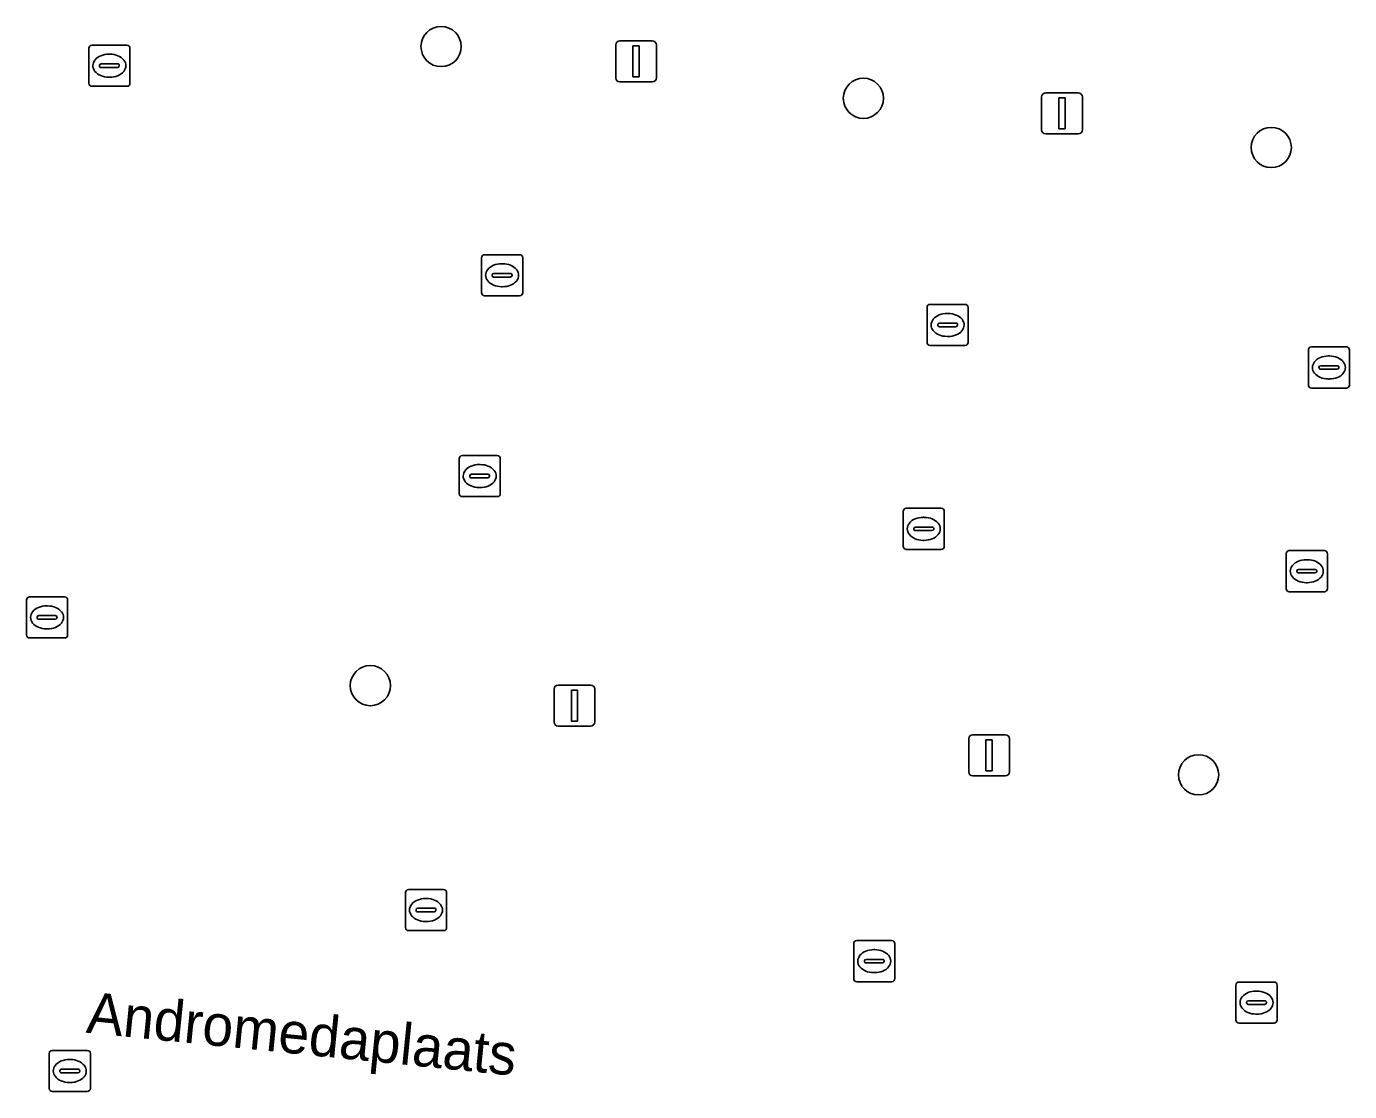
# Model space of a CAD drawing. Extents: x 161928 to 163071, y 386474 to 387428.
# Drawn here: x 162325.39 to 162357.55, y 386781.8 to 386807.71 of the extents above; entities that cross this region are included whole.
import ezdxf

# ---------------------------------------------------------------- set-up
doc = ezdxf.new("R2010")
doc.units = 0
for name, color, linetype in [('IMGEO_Boom', 7, 'Continuous'), ('IMGEO_Kolk', 7, 'Continuous'), ('IMGEO_Lichtmast', 7, 'Continuous'), ('IMGEO_Openbare_ruimte_label', 7, 'Continuous')]:
    doc.layers.add(name, color=color, linetype=linetype)

msp = doc.modelspace()

# ---------------------------------------------------------------- linework, layer by layer
at = {"layer": 'IMGEO_Boom'}
for centre in [(162335.468, 386807.22), (162345.734, 386805.961), (162355.649, 386804.765), (162333.748, 386791.675), (162353.882, 386789.504)]:
    msp.add_circle(centre, 0.489, dxfattribs=at)
at = {"layer": 'IMGEO_Kolk'}
for p, q in [((162326.902, 386806.328), (162326.902, 386807.18)), ((162326.977, 386807.254), (162327.829, 386807.254)), ((162327.39, 386807.034), (162327.415, 386807.034)), ((162327.903, 386807.18), (162327.903, 386806.328)), ((162327.161, 386806.748), (162327.161, 386806.76)), ((162327.599, 386806.711), (162327.201, 386806.711)), ((162327.204, 386806.797), (162327.602, 386806.797)), ((162327.645, 386806.76), (162327.645, 386806.748)), ((162327.413, 386806.474), (162327.388, 386806.474)), ((162327.829, 386806.254), (162326.977, 386806.254)), ((162336.45, 386801.231), (162336.45, 386802.083)), ((162336.525, 386802.157), (162337.377, 386802.157)), ((162336.938, 386801.937), (162336.963, 386801.937)), ((162337.451, 386802.083), (162337.451, 386801.231)), ((162336.709, 386801.651), (162336.709, 386801.663)), ((162337.147, 386801.614), (162336.749, 386801.614)), ((162336.752, 386801.7), (162337.15, 386801.7)), ((162337.193, 386801.663), (162337.193, 386801.651)), ((162336.961, 386801.377), (162336.936, 386801.377)), ((162337.377, 386801.157), (162336.525, 386801.157)), ((162347.356, 386800.948), (162348.208, 386800.948)), ((162347.281, 386800.022), (162347.281, 386800.874)), ((162347.769, 386800.728), (162347.794, 386800.728)), ((162348.282, 386800.874), (162348.282, 386800.022)), ((162347.54, 386800.442), (162347.54, 386800.454)), ((162347.978, 386800.405), (162347.58, 386800.405)), ((162347.583, 386800.491), (162347.981, 386800.491)), ((162348.024, 386800.454), (162348.024, 386800.442)), ((162348.208, 386799.948), (162347.356, 386799.948)), ((162347.792, 386800.168), (162347.767, 386800.168)), ((162356.551, 386798.987), (162356.551, 386799.839)), ((162356.626, 386799.913), (162357.478, 386799.913)), ((162357.039, 386799.693), (162357.064, 386799.693)), ((162357.552, 386799.839), (162357.552, 386798.987)), ((162356.81, 386799.407), (162356.81, 386799.419)), ((162357.248, 386799.37), (162356.85, 386799.37)), ((162356.853, 386799.456), (162357.251, 386799.456)), ((162357.294, 386799.419), (162357.294, 386799.407)), ((162357.062, 386799.133), (162357.037, 386799.133)), ((162357.478, 386798.913), (162356.626, 386798.913)), ((162335.905, 386796.346), (162335.905, 386797.198)), ((162335.98, 386797.272), (162336.832, 386797.272)), ((162336.393, 386797.052), (162336.418, 386797.052)), ((162336.906, 386797.198), (162336.906, 386796.346)), ((162336.164, 386796.766), (162336.164, 386796.778)), ((162336.602, 386796.729), (162336.204, 386796.729)), ((162336.207, 386796.815), (162336.605, 386796.815)), ((162336.648, 386796.778), (162336.648, 386796.766)), ((162336.416, 386796.492), (162336.391, 386796.492)), ((162336.832, 386796.272), (162335.98, 386796.272)), ((162346.7, 386795.062), (162346.7, 386795.914)), ((162346.775, 386795.988), (162347.627, 386795.988)), ((162347.188, 386795.768), (162347.213, 386795.768)), ((162347.701, 386795.914), (162347.701, 386795.062)), ((162346.959, 386795.482), (162346.959, 386795.494)), ((162347.397, 386795.445), (162346.999, 386795.445)), ((162347.002, 386795.531), (162347.4, 386795.531)), ((162347.443, 386795.494), (162347.443, 386795.482)), ((162347.211, 386795.208), (162347.186, 386795.208)), ((162347.627, 386794.988), (162346.775, 386794.988)), ((162356.013, 386794.032), (162356.013, 386794.884)), ((162356.088, 386794.958), (162356.94, 386794.958)), ((162357.014, 386794.884), (162357.014, 386794.032)), ((162356.272, 386794.452), (162356.272, 386794.464)), ((162356.315, 386794.501), (162356.713, 386794.501)), ((162356.501, 386794.738), (162356.526, 386794.738)), ((162356.756, 386794.464), (162356.756, 386794.452)), ((162356.71, 386794.415), (162356.312, 386794.415)), ((162356.524, 386794.178), (162356.499, 386794.178)), ((162325.462, 386793.834), (162326.314, 386793.834)), ((162356.94, 386793.958), (162356.088, 386793.958)), ((162325.387, 386792.908), (162325.387, 386793.76)), ((162325.875, 386793.614), (162325.9, 386793.614)), ((162326.388, 386793.76), (162326.388, 386792.908)), ((162325.646, 386793.328), (162325.646, 386793.34)), ((162326.084, 386793.291), (162325.686, 386793.291)), ((162325.689, 386793.377), (162326.087, 386793.377)), ((162326.13, 386793.34), (162326.13, 386793.328)), ((162325.898, 386793.054), (162325.873, 386793.054)), ((162326.314, 386792.834), (162325.462, 386792.834)), ((162334.6, 386785.789), (162334.6, 386786.641)), ((162334.675, 386786.715), (162335.527, 386786.715)), ((162335.088, 386786.495), (162335.113, 386786.495)), ((162335.601, 386786.641), (162335.601, 386785.789)), ((162334.859, 386786.209), (162334.859, 386786.221)), ((162335.297, 386786.172), (162334.899, 386786.172)), ((162334.902, 386786.258), (162335.3, 386786.258)), ((162335.343, 386786.221), (162335.343, 386786.209)), ((162335.111, 386785.935), (162335.086, 386785.935)), ((162335.527, 386785.715), (162334.675, 386785.715)), ((162345.573, 386785.472), (162346.425, 386785.472)), ((162345.498, 386784.546), (162345.498, 386785.398)), ((162345.986, 386785.252), (162346.011, 386785.252)), ((162346.499, 386785.398), (162346.499, 386784.546)), ((162345.757, 386784.966), (162345.757, 386784.978)), ((162346.195, 386784.929), (162345.797, 386784.929)), ((162345.8, 386785.015), (162346.198, 386785.015)), ((162346.241, 386784.978), (162346.241, 386784.966)), ((162346.009, 386784.692), (162345.984, 386784.692)), ((162346.425, 386784.472), (162345.573, 386784.472)), ((162354.791, 386783.537), (162354.791, 386784.389)), ((162354.866, 386784.463), (162355.718, 386784.463)), ((162355.279, 386784.243), (162355.304, 386784.243)), ((162355.792, 386784.389), (162355.792, 386783.537)), ((162355.05, 386783.957), (162355.05, 386783.969)), ((162355.488, 386783.92), (162355.09, 386783.92)), ((162355.093, 386784.006), (162355.491, 386784.006)), ((162355.534, 386783.969), (162355.534, 386783.957)), ((162355.302, 386783.683), (162355.277, 386783.683)), ((162355.718, 386783.463), (162354.866, 386783.463)), ((162325.94, 386781.874), (162325.94, 386782.726)), ((162326.015, 386782.8), (162326.867, 386782.8)), ((162326.428, 386782.58), (162326.453, 386782.58)), ((162326.941, 386782.726), (162326.941, 386781.874)), ((162326.199, 386782.294), (162326.199, 386782.306)), ((162326.637, 386782.257), (162326.239, 386782.257)), ((162326.242, 386782.343), (162326.64, 386782.343)), ((162326.683, 386782.306), (162326.683, 386782.294)), ((162326.451, 386782.02), (162326.426, 386782.02)), ((162326.867, 386781.8), (162326.015, 386781.8))]:
    msp.add_line(p, q, dxfattribs=at)
for points in [[(162326.902, 386806.328), (162326.902, 386807.18)], [(162326.977, 386807.254), (162327.829, 386807.254)], [(162327.903, 386807.18), (162327.903, 386806.328)], [(162327.829, 386806.254), (162326.977, 386806.254)], [(162336.45, 386801.231), (162336.45, 386802.083)], [(162336.525, 386802.157), (162337.377, 386802.157)], [(162337.451, 386802.083), (162337.451, 386801.231)], [(162337.377, 386801.157), (162336.525, 386801.157)], [(162347.356, 386800.948), (162348.208, 386800.948)], [(162347.281, 386800.022), (162347.281, 386800.874)], [(162348.282, 386800.874), (162348.282, 386800.022)], [(162348.208, 386799.948), (162347.356, 386799.948)], [(162356.551, 386798.987), (162356.551, 386799.839)], [(162356.626, 386799.913), (162357.478, 386799.913)], [(162357.552, 386799.839), (162357.552, 386798.987)], [(162357.478, 386798.913), (162356.626, 386798.913)], [(162335.905, 386796.346), (162335.905, 386797.198)], [(162335.98, 386797.272), (162336.832, 386797.272)], [(162336.906, 386797.198), (162336.906, 386796.346)], [(162336.832, 386796.272), (162335.98, 386796.272)], [(162346.7, 386795.062), (162346.7, 386795.914)], [(162346.775, 386795.988), (162347.627, 386795.988)], [(162347.701, 386795.914), (162347.701, 386795.062)], [(162347.627, 386794.988), (162346.775, 386794.988)], [(162356.013, 386794.032), (162356.013, 386794.884)], [(162356.088, 386794.958), (162356.94, 386794.958)], [(162357.014, 386794.884), (162357.014, 386794.032)], [(162325.462, 386793.834), (162326.314, 386793.834)], [(162356.94, 386793.958), (162356.088, 386793.958)], [(162325.387, 386792.908), (162325.387, 386793.76)], [(162326.388, 386793.76), (162326.388, 386792.908)], [(162326.314, 386792.834), (162325.462, 386792.834)], [(162334.6, 386785.789), (162334.6, 386786.641)], [(162334.675, 386786.715), (162335.527, 386786.715)], [(162335.601, 386786.641), (162335.601, 386785.789)], [(162335.527, 386785.715), (162334.675, 386785.715)], [(162345.573, 386785.472), (162346.425, 386785.472)], [(162345.498, 386784.546), (162345.498, 386785.398)], [(162346.499, 386785.398), (162346.499, 386784.546)], [(162346.425, 386784.472), (162345.573, 386784.472)], [(162354.791, 386783.537), (162354.791, 386784.389)], [(162354.866, 386784.463), (162355.718, 386784.463)], [(162355.792, 386784.389), (162355.792, 386783.537)], [(162355.718, 386783.463), (162354.866, 386783.463)], [(162325.94, 386781.874), (162325.94, 386782.726)], [(162326.015, 386782.8), (162326.867, 386782.8)], [(162326.941, 386782.726), (162326.941, 386781.874)], [(162326.867, 386781.8), (162326.015, 386781.8)]]:
    msp.add_lwpolyline(points, dxfattribs=at)
for centre, radius, start, end in [((162326.979, 386807.178), 0.0765, 91.552, 178.448), ((162326.979, 386807.178), 0.0765, 91.552, 178.448), ((162327.827, 386807.178), 0.0765, 1.552, 88.448), ((162327.827, 386807.178), 0.0765, 1.552, 88.448), ((162327.201, 386806.757), 0.0403, 85.8775, 175.7526), ((162327.198, 386806.747), 0.0366, 178.938, 274.7102), ((162327.602, 386806.754), 0.043, 264.8664, 352.4533), ((162327.606, 386806.759), 0.0386, 1.7309, 96.639), ((162326.979, 386806.33), 0.0765, 181.552, 268.448), ((162326.979, 386806.33), 0.0765, 181.552, 268.448), ((162327.827, 386806.33), 0.0765, 271.552, 358.448), ((162327.827, 386806.33), 0.0765, 271.552, 358.448), ((162336.527, 386802.081), 0.0765, 91.552, 178.448), ((162336.527, 386802.081), 0.0765, 91.552, 178.448), ((162337.375, 386802.081), 0.0765, 1.552, 88.448), ((162337.375, 386802.081), 0.0765, 1.552, 88.448), ((162336.749, 386801.66), 0.0403, 85.8775, 175.7526), ((162336.746, 386801.65), 0.0366, 178.938, 274.7102), ((162337.15, 386801.657), 0.043, 264.8664, 352.4533), ((162337.154, 386801.662), 0.0386, 1.7309, 96.639), ((162336.527, 386801.233), 0.0765, 181.552, 268.448), ((162336.527, 386801.233), 0.0765, 181.552, 268.448), ((162337.375, 386801.233), 0.0765, 271.552, 358.448), ((162337.375, 386801.233), 0.0765, 271.552, 358.448), ((162347.358, 386800.872), 0.0765, 91.552, 178.448), ((162347.358, 386800.872), 0.0765, 91.552, 178.448), ((162348.206, 386800.872), 0.0765, 1.552, 88.448), ((162348.206, 386800.872), 0.0765, 1.552, 88.448), ((162347.58, 386800.451), 0.0403, 85.8775, 175.7526), ((162347.577, 386800.441), 0.0366, 178.938, 274.7102), ((162347.981, 386800.448), 0.043, 264.8664, 352.4533), ((162347.985, 386800.453), 0.0386, 1.7309, 96.639), ((162347.358, 386800.024), 0.0765, 181.552, 268.448), ((162347.358, 386800.024), 0.0765, 181.552, 268.448), ((162348.206, 386800.024), 0.0765, 271.552, 358.448), ((162348.206, 386800.024), 0.0765, 271.552, 358.448), ((162356.628, 386799.837), 0.0765, 91.552, 178.448), ((162356.628, 386799.837), 0.0765, 91.552, 178.448), ((162357.476, 386799.837), 0.0765, 1.552, 88.448), ((162357.476, 386799.837), 0.0765, 1.552, 88.448), ((162356.85, 386799.416), 0.0403, 85.8775, 175.7526), ((162356.847, 386799.406), 0.0366, 178.938, 274.7102), ((162357.251, 386799.413), 0.043, 264.8664, 352.4533), ((162357.255, 386799.418), 0.0386, 1.7309, 96.639), ((162356.628, 386798.989), 0.0765, 181.552, 268.448), ((162356.628, 386798.989), 0.0765, 181.552, 268.448), ((162357.476, 386798.989), 0.0765, 271.552, 358.448), ((162357.476, 386798.989), 0.0765, 271.552, 358.448), ((162335.982, 386797.196), 0.0765, 91.552, 178.448), ((162335.982, 386797.196), 0.0765, 91.552, 178.448), ((162336.83, 386797.196), 0.0765, 1.552, 88.448), ((162336.83, 386797.196), 0.0765, 1.552, 88.448), ((162336.204, 386796.775), 0.0403, 85.8775, 175.7526), ((162336.201, 386796.765), 0.0366, 178.938, 274.7102), ((162336.605, 386796.772), 0.043, 264.8664, 352.4533), ((162336.609, 386796.777), 0.0386, 1.7309, 96.639), ((162335.982, 386796.348), 0.0765, 181.552, 268.448), ((162335.982, 386796.348), 0.0765, 181.552, 268.448), ((162336.83, 386796.348), 0.0765, 271.552, 358.448), ((162336.83, 386796.348), 0.0765, 271.552, 358.448), ((162346.777, 386795.912), 0.0765, 91.552, 178.448), ((162346.777, 386795.912), 0.0765, 91.552, 178.448), ((162347.625, 386795.912), 0.0765, 1.552, 88.448), ((162347.625, 386795.912), 0.0765, 1.552, 88.448), ((162346.999, 386795.491), 0.0403, 85.8775, 175.7526), ((162346.996, 386795.481), 0.0366, 178.938, 274.7102), ((162347.4, 386795.488), 0.043, 264.8664, 352.4533), ((162347.404, 386795.493), 0.0386, 1.7309, 96.639), ((162346.777, 386795.064), 0.0765, 181.552, 268.448), ((162346.777, 386795.064), 0.0765, 181.552, 268.448), ((162347.625, 386795.064), 0.0765, 271.552, 358.448), ((162347.625, 386795.064), 0.0765, 271.552, 358.448), ((162356.09, 386794.882), 0.0765, 91.552, 178.448), ((162356.09, 386794.882), 0.0765, 91.552, 178.448), ((162356.938, 386794.882), 0.0765, 1.552, 88.448), ((162356.938, 386794.882), 0.0765, 1.552, 88.448), ((162356.312, 386794.461), 0.0403, 85.8775, 175.7526), ((162356.717, 386794.463), 0.0386, 1.7309, 96.639), ((162356.309, 386794.451), 0.0366, 178.938, 274.7102), ((162356.713, 386794.458), 0.043, 264.8664, 352.4533), ((162325.464, 386793.758), 0.0765, 91.552, 178.448), ((162325.464, 386793.758), 0.0765, 91.552, 178.448), ((162326.312, 386793.758), 0.0765, 1.552, 88.448), ((162326.312, 386793.758), 0.0765, 1.552, 88.448), ((162356.09, 386794.034), 0.0765, 181.552, 268.448), ((162356.09, 386794.034), 0.0765, 181.552, 268.448), ((162356.938, 386794.034), 0.0765, 271.552, 358.448), ((162356.938, 386794.034), 0.0765, 271.552, 358.448), ((162325.686, 386793.337), 0.0403, 85.8775, 175.7526), ((162325.683, 386793.327), 0.0366, 178.938, 274.7102), ((162326.087, 386793.334), 0.043, 264.8664, 352.4533), ((162326.091, 386793.339), 0.0386, 1.7309, 96.639), ((162325.464, 386792.91), 0.0765, 181.552, 268.448), ((162325.464, 386792.91), 0.0765, 181.552, 268.448), ((162326.312, 386792.91), 0.0765, 271.552, 358.448), ((162326.312, 386792.91), 0.0765, 271.552, 358.448), ((162334.677, 386786.639), 0.0765, 91.552, 178.448), ((162334.677, 386786.639), 0.0765, 91.552, 178.448), ((162335.525, 386786.639), 0.0765, 1.552, 88.448), ((162335.525, 386786.639), 0.0765, 1.552, 88.448), ((162334.899, 386786.218), 0.0403, 85.8775, 175.7526), ((162334.896, 386786.208), 0.0366, 178.938, 274.7102), ((162335.3, 386786.215), 0.043, 264.8664, 352.4533), ((162335.304, 386786.22), 0.0386, 1.7309, 96.639), ((162334.677, 386785.791), 0.0765, 181.552, 268.448), ((162334.677, 386785.791), 0.0765, 181.552, 268.448), ((162335.525, 386785.791), 0.0765, 271.552, 358.448), ((162335.525, 386785.791), 0.0765, 271.552, 358.448), ((162345.575, 386785.396), 0.0765, 91.552, 178.448), ((162345.575, 386785.396), 0.0765, 91.552, 178.448), ((162346.423, 386785.396), 0.0765, 1.552, 88.448), ((162346.423, 386785.396), 0.0765, 1.552, 88.448), ((162345.797, 386784.975), 0.0403, 85.8775, 175.7526), ((162345.794, 386784.965), 0.0366, 178.938, 274.7102), ((162346.198, 386784.972), 0.043, 264.8664, 352.4533), ((162346.202, 386784.977), 0.0386, 1.7309, 96.639), ((162345.575, 386784.548), 0.0765, 181.552, 268.448), ((162345.575, 386784.548), 0.0765, 181.552, 268.448), ((162346.423, 386784.548), 0.0765, 271.552, 358.448), ((162346.423, 386784.548), 0.0765, 271.552, 358.448), ((162354.868, 386784.387), 0.0765, 91.552, 178.448), ((162354.868, 386784.387), 0.0765, 91.552, 178.448), ((162355.716, 386784.387), 0.0765, 1.552, 88.448), ((162355.716, 386784.387), 0.0765, 1.552, 88.448), ((162355.09, 386783.966), 0.0403, 85.8775, 175.7526), ((162355.087, 386783.956), 0.0366, 178.938, 274.7102), ((162355.491, 386783.963), 0.043, 264.8664, 352.4533), ((162355.495, 386783.968), 0.0386, 1.7309, 96.639), ((162354.868, 386783.539), 0.0765, 181.552, 268.448), ((162354.868, 386783.539), 0.0765, 181.552, 268.448), ((162355.716, 386783.539), 0.0765, 271.552, 358.448), ((162355.716, 386783.539), 0.0765, 271.552, 358.448), ((162326.017, 386782.724), 0.0765, 91.552, 178.448), ((162326.017, 386782.724), 0.0765, 91.552, 178.448), ((162326.865, 386782.724), 0.0765, 1.552, 88.448), ((162326.865, 386782.724), 0.0765, 1.552, 88.448), ((162326.239, 386782.303), 0.0403, 85.8775, 175.7526), ((162326.236, 386782.293), 0.0366, 178.938, 274.7102), ((162326.64, 386782.3), 0.043, 264.8664, 352.4533), ((162326.644, 386782.305), 0.0386, 1.7309, 96.639), ((162326.017, 386781.876), 0.0765, 181.552, 268.448), ((162326.017, 386781.876), 0.0765, 181.552, 268.448), ((162326.865, 386781.876), 0.0765, 271.552, 358.448), ((162326.865, 386781.876), 0.0765, 271.552, 358.448)]:
    msp.add_arc(centre, radius, start, end, dxfattribs=at)
for centre, major_axis, ratio, start_param, end_param in [((162327.389, 386806.754), (-0.387, 0.002), 0.722429, 4.712389, 7.853982), ((162327.414, 386806.754), (-0.39, 0.002), 0.717154, 1.570796, 4.712389), ((162336.937, 386801.657), (-0.387, 0.002), 0.722429, 4.712389, 7.853982), ((162336.962, 386801.657), (-0.39, 0.002), 0.717154, 1.570796, 4.712389), ((162347.768, 386800.448), (-0.387, 0.002), 0.722429, 4.712389, 7.853982), ((162347.793, 386800.448), (-0.39, 0.002), 0.717154, 1.570796, 4.712389), ((162357.038, 386799.413), (-0.387, 0.002), 0.722429, 4.712389, 7.853982), ((162357.063, 386799.413), (-0.39, 0.002), 0.717154, 1.570796, 4.712389), ((162336.392, 386796.772), (-0.387, 0.002), 0.722429, 4.712389, 7.853982), ((162336.417, 386796.772), (-0.39, 0.002), 0.717154, 1.570796, 4.712389), ((162347.187, 386795.488), (-0.387, 0.002), 0.722429, 4.712389, 7.853982), ((162347.212, 386795.488), (-0.39, 0.002), 0.717154, 1.570796, 4.712389), ((162356.5, 386794.458), (-0.387, 0.002), 0.722429, 4.712389, 7.853982), ((162356.525, 386794.458), (-0.39, 0.002), 0.717154, 1.570796, 4.712389), ((162325.874, 386793.334), (-0.387, 0.002), 0.722429, 4.712389, 7.853982), ((162325.899, 386793.334), (-0.39, 0.002), 0.717154, 1.570796, 4.712389), ((162335.087, 386786.215), (-0.387, 0.002), 0.722429, 4.712389, 7.853982), ((162335.112, 386786.215), (-0.39, 0.002), 0.717154, 1.570796, 4.712389), ((162345.985, 386784.972), (-0.387, 0.002), 0.722429, 4.712389, 7.853982), ((162346.01, 386784.972), (-0.39, 0.002), 0.717154, 1.570796, 4.712389), ((162355.278, 386783.963), (-0.387, 0.002), 0.722429, 4.712389, 7.853982), ((162355.303, 386783.963), (-0.39, 0.002), 0.717154, 1.570796, 4.712389), ((162326.427, 386782.3), (-0.387, 0.002), 0.722429, 4.712389, 7.853982), ((162326.452, 386782.3), (-0.39, 0.002), 0.717154, 1.570796, 4.712389)]:
    msp.add_ellipse(centre, major_axis=major_axis, ratio=ratio, start_param=start_param, end_param=end_param, dxfattribs=at)
at = {"layer": 'IMGEO_Lichtmast'}
for p, q in [((162339.812, 386807.359), (162340.602, 386807.359)), ((162340.602, 386807.359), (162339.812, 386807.359)), ((162339.712, 386806.459), (162339.712, 386807.259)), ((162339.712, 386807.259), (162339.712, 386806.459)), ((162340.702, 386807.259), (162340.702, 386806.459)), ((162340.702, 386806.459), (162340.702, 386807.259)), ((162340.602, 386806.359), (162339.812, 386806.359)), ((162339.812, 386806.359), (162340.602, 386806.359)), ((162350.167, 386806.094), (162350.957, 386806.094)), ((162350.957, 386806.094), (162350.167, 386806.094)), ((162350.067, 386805.194), (162350.067, 386805.994)), ((162350.067, 386805.994), (162350.067, 386805.194)), ((162351.057, 386805.994), (162351.057, 386805.194)), ((162351.057, 386805.194), (162351.057, 386805.994)), ((162350.957, 386805.094), (162350.167, 386805.094)), ((162350.167, 386805.094), (162350.957, 386805.094)), ((162338.215, 386790.788), (162338.215, 386791.588)), ((162338.215, 386791.588), (162338.215, 386790.788)), ((162338.315, 386791.688), (162339.105, 386791.688)), ((162339.105, 386791.688), (162338.315, 386791.688)), ((162339.205, 386791.588), (162339.205, 386790.788)), ((162339.205, 386790.788), (162339.205, 386791.588)), ((162339.105, 386790.688), (162338.315, 386790.688)), ((162338.315, 386790.688), (162339.105, 386790.688)), ((162348.294, 386789.578), (162348.294, 386790.378)), ((162348.294, 386790.378), (162348.294, 386789.578)), ((162348.394, 386790.478), (162349.184, 386790.478)), ((162349.184, 386790.478), (162348.394, 386790.478)), ((162349.284, 386790.378), (162349.284, 386789.578)), ((162349.284, 386789.578), (162349.284, 386790.378)), ((162349.184, 386789.478), (162348.394, 386789.478)), ((162348.394, 386789.478), (162349.184, 386789.478))]:
    msp.add_line(p, q, dxfattribs=at)
for points in [[(162340.132, 386807.234), (162340.282, 386807.234), (162340.282, 386806.484), (162340.132, 386806.484), (162340.132, 386807.234)], [(162350.487, 386805.969), (162350.637, 386805.969), (162350.637, 386805.219), (162350.487, 386805.219), (162350.487, 386805.969)], [(162338.635, 386791.563), (162338.785, 386791.563), (162338.785, 386790.813), (162338.635, 386790.813), (162338.635, 386791.563)], [(162348.714, 386790.353), (162348.864, 386790.353), (162348.864, 386789.603), (162348.714, 386789.603), (162348.714, 386790.353)]]:
    msp.add_lwpolyline(points, dxfattribs=at)
for centre, start, end in [((162339.812, 386807.259), 90, 180), ((162339.812, 386807.259), 90, 180), ((162340.602, 386807.259), 0, 90), ((162340.602, 386807.259), 360, 90), ((162339.812, 386806.459), 180, 270), ((162339.812, 386806.459), 180, 270), ((162340.602, 386806.459), 270, 0), ((162340.602, 386806.459), 270, 0), ((162350.167, 386805.994), 90, 180), ((162350.167, 386805.994), 90, 180), ((162350.957, 386805.994), 0, 90), ((162350.957, 386805.994), 360, 90), ((162350.167, 386805.194), 180, 270), ((162350.167, 386805.194), 180, 270), ((162350.957, 386805.194), 270, 0), ((162350.957, 386805.194), 270, 0), ((162338.315, 386791.588), 90, 180), ((162338.315, 386791.588), 90, 180), ((162339.105, 386791.588), 0, 90), ((162339.105, 386791.588), 360, 90), ((162338.315, 386790.788), 180, 270), ((162338.315, 386790.788), 180, 270), ((162339.105, 386790.788), 270, 0), ((162339.105, 386790.788), 270, 0), ((162348.394, 386790.378), 90, 180), ((162348.394, 386790.378), 90, 180), ((162349.184, 386790.378), 0, 90), ((162349.184, 386790.378), 360, 90), ((162348.394, 386789.578), 180, 270), ((162348.394, 386789.578), 180, 270), ((162349.184, 386789.578), 270, 0), ((162349.184, 386789.578), 270, 0)]:
    msp.add_arc(centre, 0.1, start, end, dxfattribs=at)

# ---------------------------------------------------------------- texts
at = {"layer": 'IMGEO_Openbare_ruimte_label'}
msp.add_text('Andromedaplaats', height=1, rotation=354.2609, dxfattribs=at).set_placement((162326.819, 386783.233))

doc.saveas('drawing.dxf')
